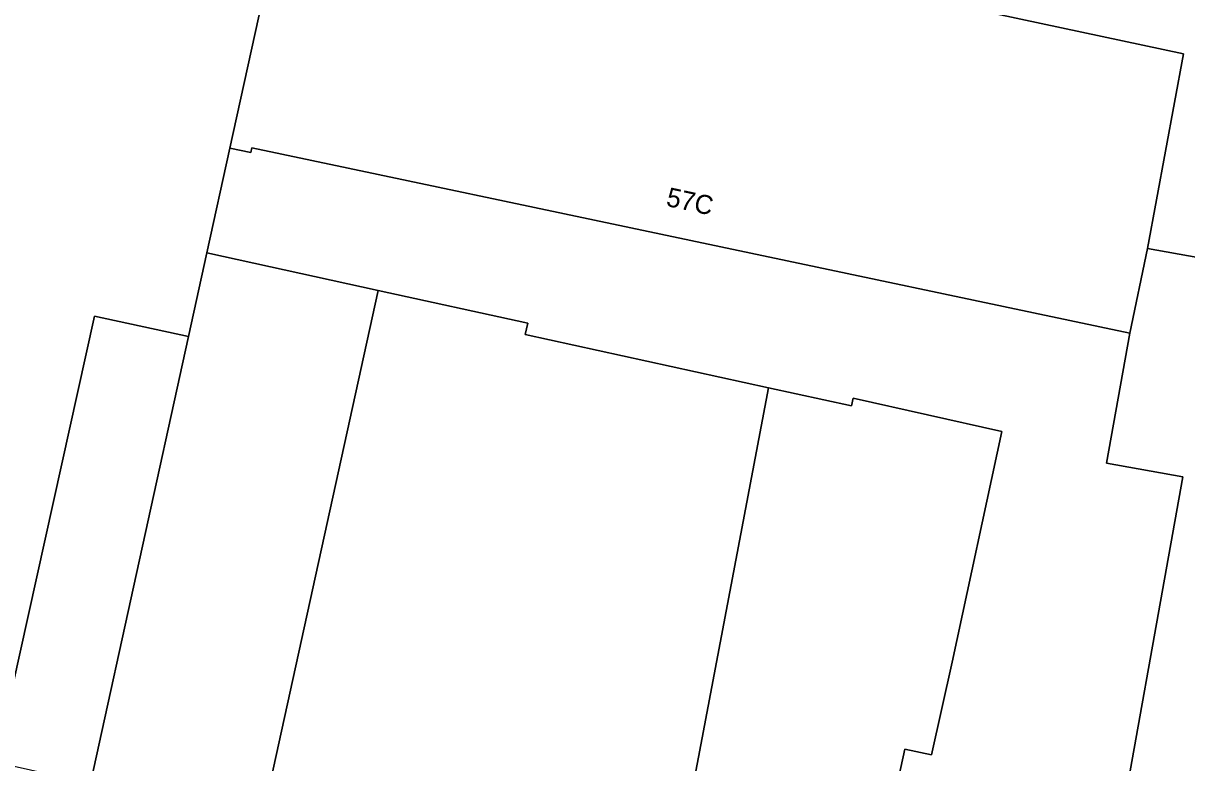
# Model space of a CAD drawing. Extents: x 163008 to 163854, y 382777 to 383982.
# Drawn here: x 163225.4 to 163286.5, y 382886.5 to 382925.4 of the extents above; entities that cross this region are included whole.
import ezdxf

# ---------------------------------------------------------------- set-up
doc = ezdxf.new("R2010")
doc.units = 0
for name, color, linetype in [('IMGEO_Erf', 7, 'Continuous'), ('IMGEO_Pand', 7, 'Continuous'), ('IMGEO_Pand_nummerreeks', 7, 'Continuous')]:
    doc.layers.add(name, color=color, linetype=linetype)

msp = doc.modelspace()

# ---------------------------------------------------------------- linework, layer by layer
at = {"layer": 'IMGEO_Erf'}
for points in [[(163268.992, 382927.522), (163286.324, 382923.801), (163284.437, 382913.579), (163299.133, 382910.949)], [(163282.354, 382879.574), (163286.289, 382901.565), (163282.284, 382902.287), (163283.508, 382909.13), (163237.378, 382918.873), (163237.325, 382918.621), (163236.225, 382918.854), (163235.004, 382913.346), (163244.014, 382911.371), (163251.869, 382909.649), (163251.739, 382909.058), (163264.521, 382906.256), (163268.883, 382905.3), (163268.972, 382905.708), (163276.784, 382903.964), (163274.167, 382891.838), (163273.096, 382886.953), (163271.691, 382887.261), (163270.546, 382882.039)]]:
    msp.add_lwpolyline(points, dxfattribs=at)
msp.add_lwpolyline([(163229.114, 382910.023), (163223.9, 382886.575), (163224.179, 382886.513), (163228.707, 382885.506), (163228.901, 382885.463), (163234.048, 382908.941)], close=True, dxfattribs=at)
at = {"layer": 'IMGEO_Pand'}
for points in [[(163239.619, 382934.325), (163239.465, 382934.363), (163208.003, 382943.747), (163202.115, 382945.503), (163196.319, 382947.232), (163191.708, 382932.235), (163203.53, 382928.6), (163196.362, 382905.287), (163188.507, 382907.928), (163186.696, 382902.466), (163193.274, 382900.911), (163191.481, 382893.329), (163191.731, 382893.27), (163191.834, 382893.704), (163195.53, 382892.882), (163196.287, 382892.714), (163196.54, 382892.658), (163223.9, 382886.575), (163229.114, 382910.023), (163234.048, 382908.941), (163235.004, 382913.346), (163236.225, 382918.854)], [(163286.324, 382923.801), (163268.992, 382927.522), (163249.516, 382931.894), (163239.619, 382934.325), (163236.225, 382918.854), (163237.325, 382918.621), (163237.378, 382918.873), (163283.508, 382909.13), (163284.437, 382913.579)], [(163237.897, 382883.491), (163244.014, 382911.371), (163235.004, 382913.346), (163234.048, 382908.941), (163228.901, 382885.463)], [(163283.508, 382909.13), (163282.284, 382902.287), (163286.289, 382901.565), (163282.354, 382879.574), (163281.473, 382874.652), (163289.492, 382873.217), (163289.456, 382873.015), (163292.263, 382872.512), (163293.144, 382877.434), (163297.159, 382899.871), (163299.133, 382910.949), (163284.437, 382913.579)], [(163264.521, 382906.256), (163251.739, 382909.058), (163251.869, 382909.649), (163244.014, 382911.371), (163237.897, 382883.491), (163238.577, 382883.342), (163257.896, 382879.106), (163259.319, 382878.794)], [(163274.167, 382891.838), (163276.784, 382903.964), (163268.972, 382905.708), (163268.883, 382905.3), (163264.521, 382906.256), (163259.319, 382878.794), (163263.157, 382877.953), (163266.807, 382877.152), (163268.014, 382876.887), (163269.339, 382876.597), (163269.415, 382876.944), (163270.386, 382881.377), (163270.913, 382881.261), (163271.058, 382881.927), (163270.546, 382882.039), (163271.691, 382887.261), (163273.096, 382886.953)]]:
    msp.add_lwpolyline(points, close=True, dxfattribs=at)

# ---------------------------------------------------------------- texts
at = {"layer": 'IMGEO_Pand_nummerreeks'}
msp.add_text('57C', height=1, rotation=347.87621, dxfattribs=at).set_placement((163259.098, 382915.823))

doc.saveas('drawing.dxf')
